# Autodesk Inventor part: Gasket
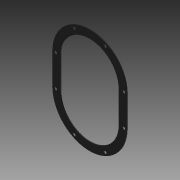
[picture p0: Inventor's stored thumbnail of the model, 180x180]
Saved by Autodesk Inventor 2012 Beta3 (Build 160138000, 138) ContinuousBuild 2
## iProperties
Created: 2010-12
Part Number: Gasket
Material: Rubber
Document SubType Name: Modeling
Designer: Thom Tremblay
Mass: 7.85962 g
Surface Area: 147.076 cm^2
Volume: 8.4512 cm^3
Density: 0.93 g/cm^3
Author: Thom Tremblay
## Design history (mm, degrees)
sketch "Sketch1"
  geometry: L1 (-60, 33.338)-(-60, -16.662) reference; L2 (60, -16.662)-(60, 33.338) reference; L3 (-46.998, -16.662)-(-46.998, 33.338) reference; L4 (46.998, 33.338)-(46.998, -16.662) reference; C1 r 1.621 at (-55, -17.463) reference; C2 r 1.621 at (-25, -66.452) reference; C3 r 1.621 at (25, -66.452) reference; C4 r 1.621 at (55, -17.462) reference; C5 r 1.621 at (55, 33.338) reference; C6 r 1.621 at (25, 82.327) reference; C7 r 1.621 at (-25, 82.327) reference; C8 r 1.621 at (-55, 33.337) reference; A1 r 60 centre (0, -16.662) between (-60, -16.662) and (-18.704, -73.673) reference; A2 r 60 centre (0, 33.338) between (60, 33.338) and (-60, 33.338) reference; A3 r 46.998 centre (0, -16.662) between (-46.998, -16.662) and (46.998, -16.662) reference; A4 r 46.998 centre (0, 33.338) between (46.998, 33.338) and (-46.998, 33.338) reference; A5 r 60.082 centre (0, -16.662) between (-16.251, -74.505) and (16.251, -74.505) reference; A6 r 60 centre (0, -16.662) between (18.704, -73.673) and (60, -16.662) reference; 21 further points
extrude "Extrusion1" new body sketch "Sketch1" distance "d0" = 1.27; taper "d1" = 0 deg
node "Hole4"
body "Solid1"
node "Reference1"
sketch "Sketch4"
  geometry: 8 further points
hole "Hole3" sketch "Sketch4" diameter "d16" = 4.49999; stored, may be unused: countersink angle "d20" = 82 deg, drill point angle "d22" = 0 deg; dims "d17" = 19.05, "d18" = 9.525, "d19" = 6.35, "d21" = 25.4
